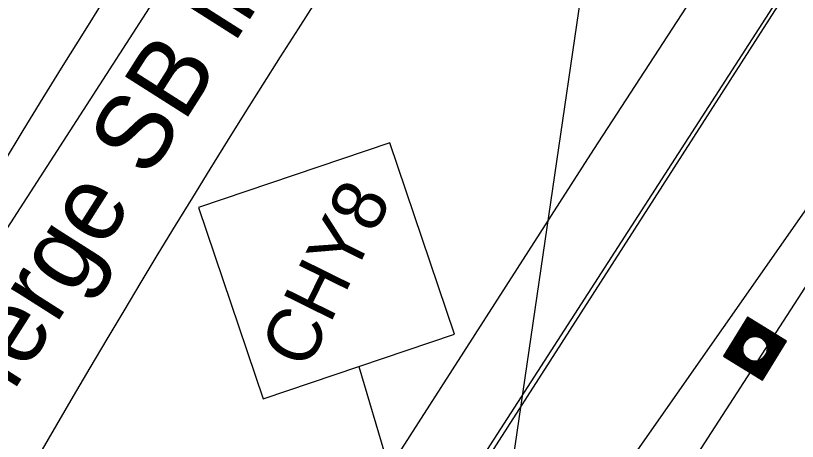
# Model space of a CAD drawing. Extents: x 14104283 to 14128447, y 8633203 to 8671666.
# Drawn here: x 14119211.5 to 14119316, y 8669105.5 to 8669162.4 of the extents above; entities that cross this region are included whole.
import ezdxf

# ---------------------------------------------------------------- set-up
doc = ezdxf.new("R2010")
doc.units = 0
for name, color, linetype in [('dsnCellElements', 7, 'Continuous'), ('dsnNonPlotable', 7, 'Continuous'), ('dsnPaintExistingEdgeLineRightWhite', 7, 'Continuous'), ('dsnShadingPaved', 7, 'Continuous'), ('dsnStdLabel', 7, 'Continuous'), ('dsnStgShadingPrevPav', 7, 'Continuous'), ('dsnStgShadingPropPav', 7, 'Continuous'), ('dsnTapeExistingChannelizingLaneYellow', 7, 'Continuous'), ('dsnTapePlaceChannelizingYellow', 7, 'Continuous')]:
    doc.layers.add(name, color=color, linetype=linetype)

msp = doc.modelspace()

# ---------------------------------------------------------------- linework, layer by layer
at = {"layer": 'dsnCellElements'}
msp.add_circle((14119310.36, 8669117.87), 1.65, dxfattribs=at)
at = {"layer": 'dsnNonPlotable'}
msp.add_lwpolyline([(14118774.15, 8669147.84), (14119001.66, 8670698.74), (14119501.31, 8670625.45), (14119273.81, 8669074.54)], close=True, dxfattribs=at)
at = {"layer": 'dsnPaintExistingEdgeLineRightWhite'}
msp.add_lwpolyline([(14119412.15, 8669317.07), (14119387.62, 8669279), (14119355.61, 8669229.26), (14119328.75, 8669187.71), (14119296.91, 8669137.95), (14119267.45, 8669092.09), (14119237.9, 8669046.84), (14119206.91, 8668999.35), (14119178.97, 8668956.72), (14119155.37, 8668919.99)], dxfattribs=at)
at = {"layer": 'dsnShadingPaved'}
for p, q in [((14119155.5, 8668919.9), (14119497.22, 8669449.29)), ((14119403.44, 8669259.76), (14119219.81, 8668997.42)), ((14119292.6, 8669088.16), (14119403.44, 8669259.76))]:
    msp.add_line(p, q, dxfattribs=at)
at = {"layer": 'dsnStdLabel'}
for p, q in [((14119150.89, 8669041.84), (14119324.44, 8669310.7)), ((14119257.4, 8669115.49), (14119274.51, 8669058))]:
    msp.add_line(p, q, dxfattribs=at)
msp.add_lwpolyline([(14119244.61, 8669111.16), (14119270.19, 8669119.81), (14119261.53, 8669145.39), (14119235.96, 8669136.74)], close=True, dxfattribs=at)
for points in [[(14119311.37, 8669113.66), (14119314.58, 8669118.88), (14119309.36, 8669122.08), (14119306.15, 8669116.86), (14119311.37, 8669113.66)], [(14119311.37, 8669113.66), (14119314.57, 8669118.88), (14119309.36, 8669122.08), (14119306.16, 8669116.86), (14119311.37, 8669113.66)], [(14119311.36, 8669113.66), (14119314.57, 8669118.88), (14119309.36, 8669122.07), (14119306.16, 8669116.87), (14119311.37, 8669113.66)], [(14119311.41, 8669113.8), (14119314.52, 8669118.87), (14119309.37, 8669122.03), (14119306.21, 8669116.88), (14119311.39, 8669113.69)], [(14119311.4, 8669113.84), (14119314.48, 8669118.85), (14119309.38, 8669121.98), (14119306.25, 8669116.89), (14119311.41, 8669113.72)], [(14119311.39, 8669113.89), (14119314.43, 8669118.84), (14119309.39, 8669121.94), (14119306.3, 8669116.9), (14119311.43, 8669113.75)], [(14119311.38, 8669113.93), (14119314.39, 8669118.83), (14119309.4, 8669121.89), (14119306.34, 8669116.91), (14119311.41, 8669113.8)], [(14119311.37, 8669113.98), (14119314.34, 8669118.82), (14119309.41, 8669121.85), (14119306.39, 8669116.92), (14119311.4, 8669113.84)], [(14119311.35, 8669114.02), (14119314.29, 8669118.81), (14119309.42, 8669121.8), (14119306.43, 8669116.93), (14119311.39, 8669113.89)], [(14119311.34, 8669114.07), (14119314.25, 8669118.8), (14119309.43, 8669121.76), (14119306.48, 8669116.94), (14119311.38, 8669113.93)], [(14119311.33, 8669114.11), (14119314.2, 8669118.79), (14119309.45, 8669121.71), (14119306.52, 8669116.95), (14119311.37, 8669113.98)], [(14119311.32, 8669114.16), (14119314.16, 8669118.78), (14119309.46, 8669121.67), (14119306.57, 8669116.96), (14119311.35, 8669114.02)], [(14119311.31, 8669114.21), (14119314.11, 8669118.77), (14119309.47, 8669121.62), (14119306.61, 8669116.97), (14119311.34, 8669114.07)], [(14119311.3, 8669114.25), (14119314.07, 8669118.76), (14119309.48, 8669121.58), (14119306.66, 8669116.99), (14119311.33, 8669114.11)], [(14119311.29, 8669114.3), (14119314.02, 8669118.75), (14119309.49, 8669121.53), (14119306.7, 8669117), (14119311.32, 8669114.16)], [(14119311.28, 8669114.34), (14119313.98, 8669118.73), (14119309.5, 8669121.48), (14119306.75, 8669117.01), (14119311.31, 8669114.21)], [(14119311.27, 8669114.39), (14119313.93, 8669118.72), (14119309.51, 8669121.44), (14119306.8, 8669117.02), (14119311.3, 8669114.25)], [(14119311.26, 8669114.43), (14119313.89, 8669118.71), (14119309.52, 8669121.39), (14119306.84, 8669117.03), (14119311.29, 8669114.3)], [(14119311.25, 8669114.48), (14119313.84, 8669118.7), (14119309.53, 8669121.35), (14119306.89, 8669117.04), (14119311.28, 8669114.34)], [(14119311.24, 8669114.52), (14119313.8, 8669118.69), (14119309.54, 8669121.3), (14119306.93, 8669117.05), (14119311.27, 8669114.39)], [(14119311.22, 8669114.57), (14119313.75, 8669118.68), (14119309.55, 8669121.26), (14119306.98, 8669117.06), (14119311.26, 8669114.43)], [(14119311.21, 8669114.61), (14119313.7, 8669118.67), (14119309.56, 8669121.21), (14119307.02, 8669117.07), (14119311.25, 8669114.48)], [(14119311.2, 8669114.66), (14119313.66, 8669118.66), (14119309.58, 8669121.17), (14119307.07, 8669117.08), (14119311.24, 8669114.52)], [(14119311.19, 8669114.7), (14119313.61, 8669118.65), (14119309.59, 8669121.12), (14119307.11, 8669117.09), (14119311.22, 8669114.57)], [(14119311.18, 8669114.75), (14119313.57, 8669118.64), (14119309.6, 8669121.08), (14119307.16, 8669117.1), (14119311.21, 8669114.61)], [(14119311.17, 8669114.8), (14119313.52, 8669118.63), (14119309.61, 8669121.03), (14119307.2, 8669117.12), (14119311.2, 8669114.66)], [(14119311.16, 8669114.84), (14119313.48, 8669118.62), (14119309.62, 8669120.99), (14119307.25, 8669117.13), (14119311.19, 8669114.7)], [(14119311.15, 8669114.89), (14119313.43, 8669118.6), (14119309.63, 8669120.94), (14119307.29, 8669117.14), (14119311.18, 8669114.75)], [(14119311.14, 8669114.93), (14119313.39, 8669118.59), (14119309.64, 8669120.89), (14119307.34, 8669117.15), (14119311.17, 8669114.8)], [(14119311.13, 8669114.98), (14119313.34, 8669118.58), (14119309.65, 8669120.85), (14119307.39, 8669117.16), (14119311.16, 8669114.84)], [(14119311.12, 8669115.02), (14119313.3, 8669118.57), (14119309.66, 8669120.8), (14119307.43, 8669117.17), (14119311.15, 8669114.89)], [(14119311.11, 8669115.07), (14119313.25, 8669118.56), (14119309.67, 8669120.76), (14119307.48, 8669117.18), (14119311.14, 8669114.93)], [(14119311.09, 8669115.11), (14119313.21, 8669118.55), (14119309.68, 8669120.71), (14119307.52, 8669117.19), (14119311.13, 8669114.98)], [(14119311.08, 8669115.16), (14119313.16, 8669118.54), (14119309.69, 8669120.67), (14119307.57, 8669117.2), (14119311.12, 8669115.02)], [(14119311.07, 8669115.2), (14119313.11, 8669118.53), (14119309.71, 8669120.62), (14119307.61, 8669117.21), (14119311.11, 8669115.07)], [(14119311.06, 8669115.25), (14119313.07, 8669118.52), (14119309.72, 8669120.58), (14119307.66, 8669117.22), (14119311.09, 8669115.11)], [(14119311.05, 8669115.29), (14119313.02, 8669118.51), (14119309.73, 8669120.53), (14119307.7, 8669117.23), (14119311.08, 8669115.16)], [(14119311.04, 8669115.34), (14119312.98, 8669118.5), (14119309.74, 8669120.49), (14119307.75, 8669117.25), (14119311.07, 8669115.2)], [(14119311.03, 8669115.39), (14119312.93, 8669118.49), (14119309.75, 8669120.44), (14119307.79, 8669117.26), (14119311.06, 8669115.25)], [(14119311.02, 8669115.43), (14119312.89, 8669118.47), (14119309.76, 8669120.4), (14119307.84, 8669117.27), (14119311.05, 8669115.29)], [(14119311.01, 8669115.48), (14119312.84, 8669118.46), (14119309.77, 8669120.35), (14119307.88, 8669117.28), (14119311.04, 8669115.34)], [(14119311, 8669115.52), (14119312.8, 8669118.45), (14119309.78, 8669120.3), (14119307.93, 8669117.29), (14119311.03, 8669115.39)], [(14119310.99, 8669115.57), (14119312.75, 8669118.44), (14119309.79, 8669120.26), (14119307.98, 8669117.3), (14119311.02, 8669115.43)], [(14119310.98, 8669115.61), (14119312.71, 8669118.43), (14119309.8, 8669120.21), (14119308.02, 8669117.31), (14119311.01, 8669115.48)], [(14119310.96, 8669115.66), (14119312.66, 8669118.42), (14119309.81, 8669120.17), (14119308.07, 8669117.32), (14119311, 8669115.52)], [(14119310.95, 8669115.7), (14119312.62, 8669118.41), (14119309.82, 8669120.12), (14119308.11, 8669117.33), (14119310.99, 8669115.57)], [(14119310.94, 8669119.4), (14119309.84, 8669120.08), (14119309.16, 8669118.97)], [(14119310.8, 8669119.44), (14119309.85, 8669120.03), (14119309.26, 8669119.07)], [(14119310.7, 8669119.47), (14119309.86, 8669119.99), (14119309.34, 8669119.14)], [(14119310.61, 8669119.49), (14119309.87, 8669119.94), (14119309.41, 8669119.2)], [(14119310.53, 8669119.5), (14119309.88, 8669119.9), (14119309.48, 8669119.24)], [(14119310.46, 8669119.5), (14119309.89, 8669119.85), (14119309.54, 8669119.28)], [(14119310.39, 8669119.5), (14119309.9, 8669119.81), (14119309.6, 8669119.32)], [(14119310.33, 8669119.5), (14119309.91, 8669119.76), (14119309.66, 8669119.34)], [(14119310.27, 8669119.5), (14119309.92, 8669119.71), (14119309.71, 8669119.37)], [(14119310.21, 8669119.5), (14119309.93, 8669119.67), (14119309.76, 8669119.39)], [(14119310.16, 8669119.49), (14119309.94, 8669119.62), (14119309.81, 8669119.41)], [(14119310.11, 8669119.48), (14119309.96, 8669119.58), (14119309.86, 8669119.43)], [(14119310.06, 8669119.48), (14119309.97, 8669119.53), (14119309.91, 8669119.44)], [(14119310.01, 8669119.47), (14119309.98, 8669119.49), (14119309.96, 8669119.45)], [(14119311.89, 8669117.29), (14119312.57, 8669118.4), (14119311.47, 8669119.08)], [(14119311.94, 8669117.43), (14119312.52, 8669118.39), (14119311.57, 8669118.98)], [(14119311.96, 8669117.53), (14119312.48, 8669118.38), (14119311.64, 8669118.89)], [(14119311.98, 8669117.62), (14119312.43, 8669118.37), (14119311.69, 8669118.82)], [(14119311.99, 8669117.7), (14119312.39, 8669118.36), (14119311.74, 8669118.76)], [(14119311.99, 8669117.78), (14119312.34, 8669118.34), (14119311.77, 8669118.69)], [(14119312, 8669117.84), (14119312.3, 8669118.33), (14119311.81, 8669118.63)], [(14119312, 8669117.91), (14119312.25, 8669118.32), (14119311.84, 8669118.58)], [(14119311.99, 8669117.97), (14119312.21, 8669118.31), (14119311.86, 8669118.52)], [(14119308.84, 8669118.45), (14119308.16, 8669117.34), (14119309.26, 8669116.67)], [(14119308.79, 8669118.31), (14119308.2, 8669117.35), (14119309.16, 8669116.77)], [(14119308.76, 8669118.21), (14119308.25, 8669117.37), (14119309.09, 8669116.85)], [(14119308.75, 8669118.12), (14119308.29, 8669117.38), (14119309.03, 8669116.92)], [(14119308.74, 8669118.04), (14119308.34, 8669117.39), (14119308.99, 8669116.99)], [(14119308.73, 8669117.97), (14119308.38, 8669117.4), (14119308.95, 8669117.05)], [(14119308.73, 8669117.9), (14119308.43, 8669117.41), (14119308.92, 8669117.11)], [(14119308.73, 8669117.84), (14119308.47, 8669117.42), (14119308.89, 8669117.16)], [(14119308.73, 8669117.78), (14119308.52, 8669117.43), (14119308.87, 8669117.22)], [(14119308.74, 8669117.72), (14119308.57, 8669117.44), (14119308.84, 8669117.27)], [(14119308.74, 8669117.67), (14119308.61, 8669117.45), (14119308.83, 8669117.32)], [(14119308.75, 8669117.62), (14119308.66, 8669117.46), (14119308.81, 8669117.37)], [(14119308.76, 8669117.57), (14119308.7, 8669117.47), (14119308.79, 8669117.42)], [(14119308.77, 8669117.52), (14119308.75, 8669117.48), (14119308.78, 8669117.46)], [(14119311.99, 8669118.02), (14119312.16, 8669118.3), (14119311.88, 8669118.47)], [(14119311.98, 8669118.08), (14119312.12, 8669118.29), (14119311.9, 8669118.42)], [(14119311.98, 8669118.13), (14119312.07, 8669118.28), (14119311.92, 8669118.37)], [(14119311.97, 8669118.18), (14119312.03, 8669118.27), (14119311.93, 8669118.33)], [(14119311.96, 8669118.22), (14119311.98, 8669118.26), (14119311.95, 8669118.28)], [(14119310.89, 8669115.98), (14119311.19, 8669116.46)], [(14119310.9, 8669115.93), (14119311.25, 8669116.5)], [(14119310.91, 8669115.89), (14119311.31, 8669116.54)], [(14119310.92, 8669115.84), (14119311.39, 8669116.6)], [(14119310.93, 8669115.79), (14119311.47, 8669116.67)], [(14119310.94, 8669115.75), (14119311.57, 8669116.77)], [(14119309.79, 8669116.34), (14119310.98, 8669115.61)], [(14119309.92, 8669116.3), (14119310.96, 8669115.66)], [(14119310.03, 8669116.27), (14119310.95, 8669115.7)], [(14119310.12, 8669116.26), (14119310.94, 8669115.75)], [(14119310.2, 8669116.25), (14119310.93, 8669115.79)], [(14119310.27, 8669116.24), (14119310.92, 8669115.84)], [(14119310.34, 8669116.24), (14119310.91, 8669115.89)], [(14119310.4, 8669116.24), (14119310.9, 8669115.93)], [(14119310.46, 8669116.24), (14119310.89, 8669115.98)], [(14119310.51, 8669116.24), (14119310.88, 8669116.02)], [(14119310.57, 8669116.25), (14119310.87, 8669116.07)], [(14119310.62, 8669116.26), (14119310.86, 8669116.11)], [(14119310.67, 8669116.27), (14119310.84, 8669116.16)], [(14119310.72, 8669116.28), (14119310.83, 8669116.2)], [(14119310.83, 8669116.2), (14119310.91, 8669116.33)], [(14119310.84, 8669116.16), (14119310.96, 8669116.35)], [(14119310.86, 8669116.11), (14119311.02, 8669116.37)], [(14119310.87, 8669116.07), (14119311.07, 8669116.4)], [(14119310.88, 8669116.02), (14119311.13, 8669116.43)]]:
    msp.add_lwpolyline(points, dxfattribs=at)
at = {"layer": 'dsnStgShadingPrevPav'}
msp.add_lwpolyline([(14119144.14, 8668920.3), (14119170.94, 8668961.91), (14119198.95, 8669005.04), (14119229.55, 8669052.67), (14119259.7, 8669099.16), (14119288.84, 8669144.53), (14119320.43, 8669193.09), (14119347.13, 8669234.7), (14119379.16, 8669285.01), (14119403.27, 8669322.21)], dxfattribs=at)
at = {"layer": 'dsnStgShadingPropPav'}
for radius, end in [(1512, 159.62671), (1488, 158.15787)]:
    msp.add_arc((14120503.02, 8668359.24), radius, 147.24256, end, dxfattribs=at)
at = {"layer": 'dsnTapeExistingChannelizingLaneYellow'}
msp.add_line((14119403.44, 8669259.76), (14119219.81, 8668997.42), dxfattribs=at)
at = {"layer": 'dsnTapePlaceChannelizingYellow'}
msp.add_line((14119292.6, 8669088.16), (14119403.44, 8669259.76), dxfattribs=at)

# ---------------------------------------------------------------- texts
at = {"layer": 'dsnStdLabel'}
for s, height, rotation, p in [('Merge SB into Outside Lane', 10, 57.6002, (14119206.91, 8669105.32)), ('CHY8', 7.2, 63.6912, (14119250.45, 8669114.85))]:
    msp.add_text(s, height=height, rotation=rotation, dxfattribs=at).set_placement(p)

doc.saveas('drawing.dxf')
